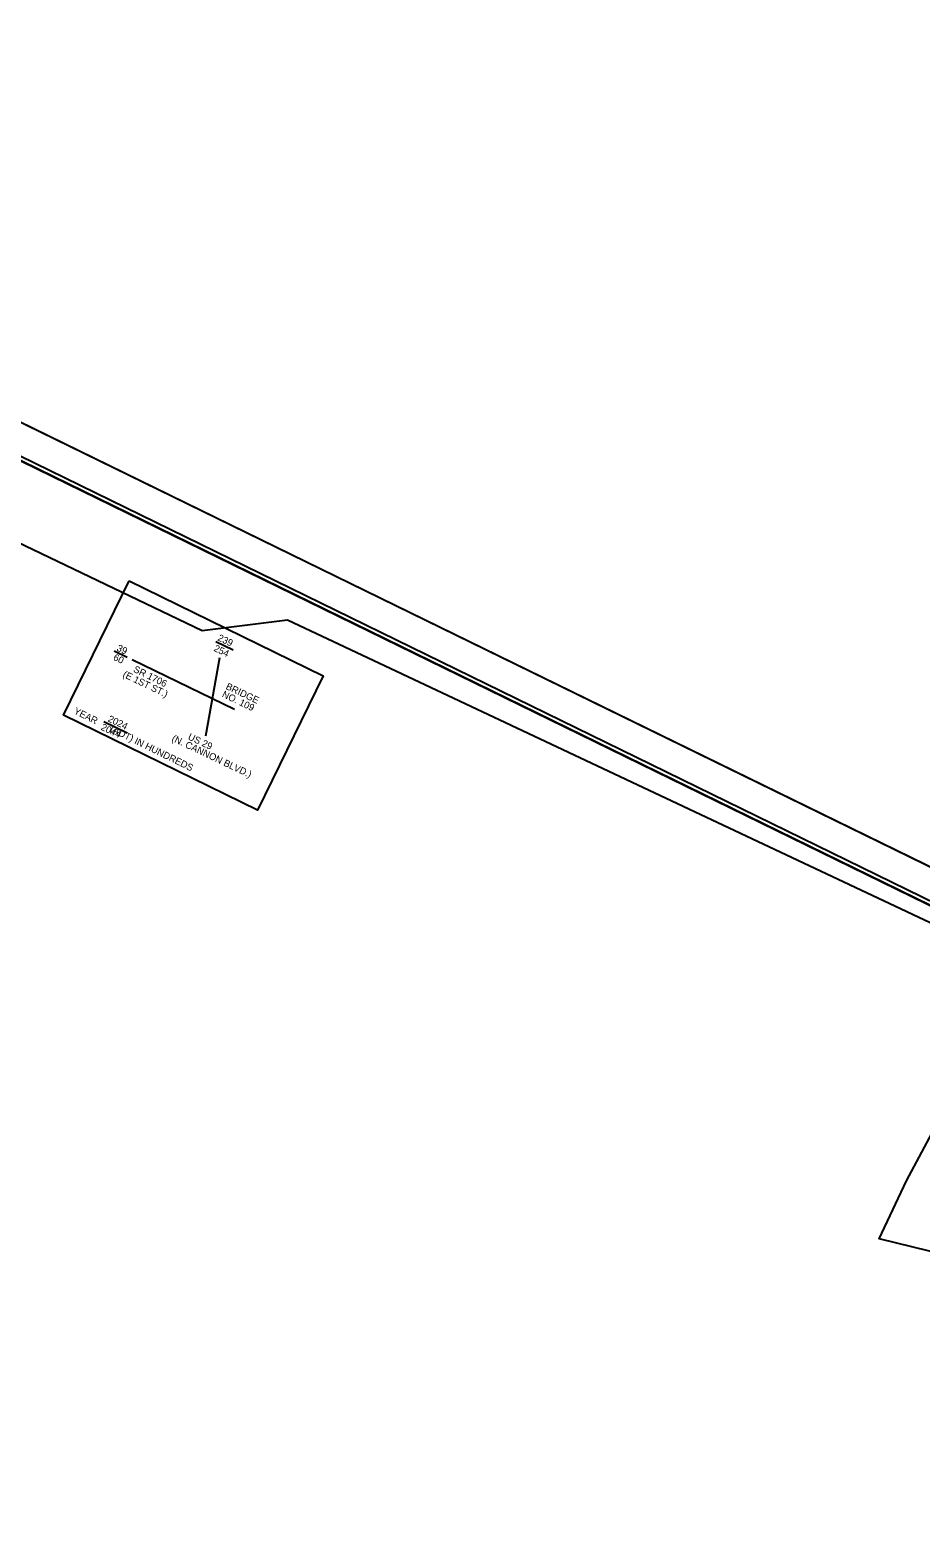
# Model space of a CAD drawing. Extents: x 1519210 to 1521378, y 637447 to 639183.
# Drawn here: x 1520219 to 1520798, y 638202 to 639183 of the extents above; entities that cross this region are included whole.
import ezdxf

# ---------------------------------------------------------------- set-up
doc = ezdxf.new("R2010")
doc.units = 0
for name, color, linetype in [('Sheet Clip Boundary CELL', 7, 'Continuous'), ('Sheet Cutting Line CELL', 7, 'Continuous'), ('Sheet Data Field CELL', 7, 'Continuous'), ('Sheet Layout Plan Border', 7, 'Continuous'), ('Sheet Plan CELL', 7, 'Continuous'), ('Sheet Plan Layout CELL', 7, 'Continuous'), ('Sheet Plot Border Inside CELL', 7, 'Continuous'), ('Sheet Plot Border Outside CELL', 7, 'Continuous')]:
    doc.layers.add(name, color=color, linetype=linetype)

msp = doc.modelspace()

# ---------------------------------------------------------------- linework, layer by layer
at = {"layer": 'Sheet Clip Boundary CELL'}
msp.add_lwpolyline([(1519956.23, 637866.66), (1520671.92, 637509.27), (1520894.79, 637860.14), (1521077.44, 638237.75), (1521090.11, 638267.88), (1521090.34, 638272.49), (1520913.04, 638361.6), (1520771.34, 638396.31), (1520789.23, 638433.99), (1520863.92, 638574.09), (1520386.4, 638798.91), (1520331.06, 638791.96), (1519849.49, 639022.82)], dxfattribs=at)
at = {"layer": 'Sheet Cutting Line CELL'}
msp.add_line((1521203.3, 638443.27), (1519690.98, 639182.91), dxfattribs=at)
at = {"layer": 'Sheet Data Field CELL'}
for p, q in [((1520339.94, 638785.13), (1520351.09, 638779.68)), ((1520273.74, 638779.05), (1520282.1, 638774.96)), ((1520333.36, 638723.69), (1520342.43, 638774.57)), ((1520285.51, 638773.41), (1520351.92, 638740.93)), ((1520266.99, 638733.07), (1520282.1, 638725.68))]:
    msp.add_line(p, q, dxfattribs=at)
msp.add_lwpolyline([(1520283.55, 638824.5), (1520409.71, 638762.8), (1520366.93, 638675.34), (1520240.78, 638737.04)], close=True, dxfattribs=at)
at = {"layer": 'Sheet Layout Plan Border'}
msp.add_lwpolyline([(1519414.26, 638124.36), (1520671.92, 637509.27), (1521040.32, 638262.52), (1520870.3, 638345.67), (1520963.21, 638535.65), (1519875.58, 639067.59)], close=True, dxfattribs=at)
at = {"layer": 'Sheet Plan CELL'}
for points in [[(1521178.17, 638430.52), (1519830.66, 639089.56), (1519369.35, 638146.33), (1520716.83, 637487.3)], [(1519369.35, 638146.33), (1519830.63, 639089.55), (1520998.45, 638518.44), (1520906.34, 638330.09), (1521086.04, 638242.2), (1520716.83, 637487.3)]]:
    msp.add_lwpolyline(points, close=True, dxfattribs=at)
at = {"layer": 'Sheet Plan Layout CELL'}
msp.add_lwpolyline([(1519830.63, 639089.55), (1519369.35, 638146.33), (1520716.82, 637487.31), (1521085.22, 638240.56), (1520870.3, 638345.67), (1520963.21, 638535.65)], close=True, dxfattribs=at)
at = {"layer": 'Sheet Plot Border Inside CELL'}
msp.add_lwpolyline([(1519230.36, 638211.5), (1520726.95, 637479.57), (1521190.47, 638427.28), (1519693.87, 639159.23)], close=True, dxfattribs=at)
at = {"layer": 'Sheet Plot Border Outside CELL'}
msp.add_lwpolyline([(1519209.9, 638199.25), (1520722.21, 637459.61), (1521203.3, 638443.27), (1519690.98, 639182.91)], close=True, dxfattribs=at)

# ---------------------------------------------------------------- texts
at = {"layer": 'Sheet Data Field CELL'}
for s, rotation, p in [('239', 334.62093, (1520340.64, 638785.96)), ('60', 334.62093, (1520272.71, 638773.22)), ('39', 334.62093, (1520274.96, 638779.27)), ('254', 334.62093, (1520338.13, 638779.09)), ('(E 1ST ST.)', 334.19229, (1520278.91, 638762.23)), ('SR 1706', 333.65397, (1520285.8, 638765.53)), ('BRIDGE ', 334.3627, (1520345.95, 638754.31)), ('NO. 109', 334.3627, (1520343.49, 638749.19)), ('YEAR      (ADT) IN HUNDREDS', 333.73897, (1520247.09, 638738.31)), ('2024', 334.62093, (1520269.22, 638733.2)), ('2044', 334.62093, (1520264.7, 638727.8)), ('US 29', 334.62093, (1520321.29, 638721.56)), ('(N. CANNON BLVD.)', 334.62093, (1520310.74, 638720.49))]:
    msp.add_text(s, height=4.48, rotation=rotation, dxfattribs=at).set_placement(p)

doc.saveas('drawing.dxf')
